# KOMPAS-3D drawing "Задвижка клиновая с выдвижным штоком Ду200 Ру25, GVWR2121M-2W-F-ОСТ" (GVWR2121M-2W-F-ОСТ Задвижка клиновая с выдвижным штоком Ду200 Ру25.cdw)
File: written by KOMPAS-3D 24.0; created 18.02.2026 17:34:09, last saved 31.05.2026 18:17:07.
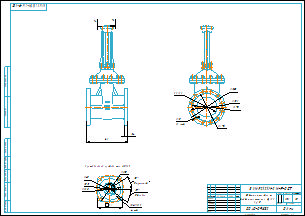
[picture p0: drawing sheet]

Document properties: Автор: R2D2; Форматы листов документа: A2; Полное имя файла: GVWR2121M-2W-F-ОСТ Задвижка клиновая с выдвижным штоком Ду200 Ру25.m3d; Масса: 130; Наименование: Задвижка клиновая с выдвижным штоком Ду200 Ру25; Количество листов документа: 1; Примечание: D040-09832

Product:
- Part/product: Задвижка клиновая с выдвижным штоком Ду200 Ру25  | designation GVWR2121M-2W-F-ОСТ
    Масса: 130
    Раздел спецификации: Прочие изделия
    Примечание: D040-09832

Views: Проекционный вид 2
Referenced files in E:\Работа\Зайцев\Для компаса\: чертеж DN.ru А3.cdt
Referenced files in E:\Работа\Зайцев\GVWR2121M-2W-F-ОСТ Задвижка клиновая 30с964нж DN.ru Ду50-300 Ру25\исходные материалы\DN200\DN200\: GVWR2121M-2W-F-ОСТ Задвижка клиновая с выдвижным штоком Ду200 Ру25.m3d
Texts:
  Присоединение привода тип АК (Б)
  чертеж DN.ru А3.cdt
  Задвижка клиновая с
  выдвижным штоком Ду200
  Ру25
  GVWR2121M-2W-F-ОСТ
  Задвижка клиновая с выдвижным штоком Ду200 Ру25
  GVWR2121M-2W-F-ОСТ Задвижка клиновая с выдвижным штоком Ду200 Ру25
Dimensions and other numbers on the sheet: 108; 45; 59; 135; 14(М12); 4 отв.; 122; 5 впадин; 5 кулачков; 1:5; 0; 1; 2; 130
